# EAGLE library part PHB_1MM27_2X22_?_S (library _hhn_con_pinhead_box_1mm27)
Pin Header Box-Type, 1.27mm/0.5"/50mil Pitch, 2x22 Circuits, single gates in schematic Note: see library description for an important note about THT-version
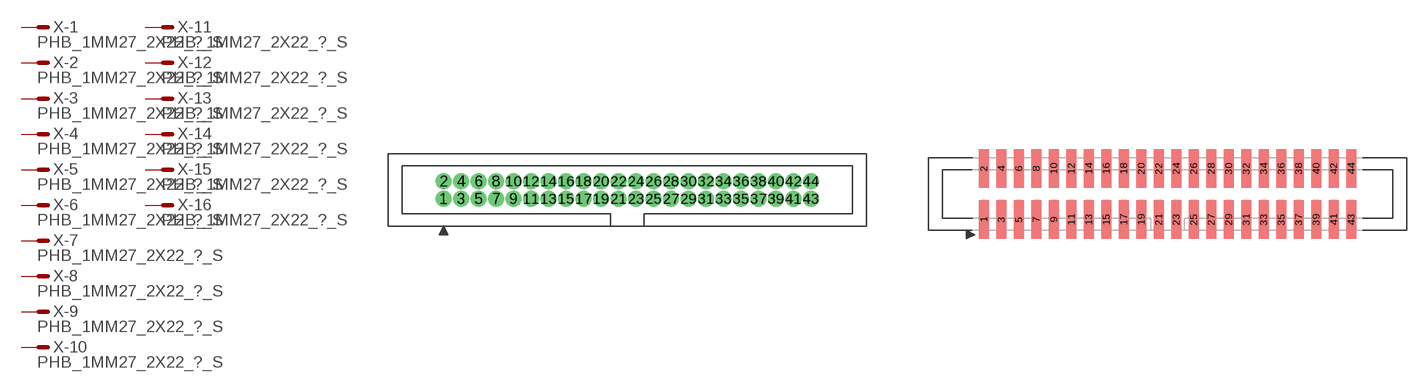
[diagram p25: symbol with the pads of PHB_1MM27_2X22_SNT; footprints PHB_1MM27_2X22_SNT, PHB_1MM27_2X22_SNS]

Designator prefix X; gates -1=M -2=M -3=M -4=M -5=M -6=M -7=M -8=M -9=M -10=M -11=M -12=M -13=M -14=M -15=M -16=M -17=M -18=M -19=M -20=M -21=M -22=M -23=M -24=M -25=M -26=M -27=M -28=M -29=M -30=M -31=M -32=M -33=M -34=M -35=M -36=M -37=M -38=M -39=M -40=M -41=M -42=M -43=M -44=M

## PHB_1MM27_2X22_SNT_S  [PHB_1MM27_2X22_SNT]
1  -1:S  pas
2  -2:S  pas
3  -3:S  pas
4  -4:S  pas
5  -5:S  pas
6  -6:S  pas
7  -7:S  pas
8  -8:S  pas
9  -9:S  pas
10  -10:S  pas
11  -11:S  pas
12  -12:S  pas
13  -13:S  pas
14  -14:S  pas
15  -15:S  pas
16  -16:S  pas
17  -17:S  pas
18  -18:S  pas
19  -19:S  pas
20  -20:S  pas
21  -21:S  pas
22  -22:S  pas
23  -23:S  pas
24  -24:S  pas
25  -25:S  pas
26  -26:S  pas
27  -27:S  pas
28  -28:S  pas
29  -29:S  pas
30  -30:S  pas
31  -31:S  pas
32  -32:S  pas
33  -33:S  pas
34  -34:S  pas
35  -35:S  pas
36  -36:S  pas
37  -37:S  pas
38  -38:S  pas
39  -39:S  pas
40  -40:S  pas
41  -41:S  pas
42  -42:S  pas
43  -43:S  pas
44  -44:S  pas

## PHB_1MM27_2X22_SNS_S  [PHB_1MM27_2X22_SNS]
Pads as for PHB_1MM27_2X22_SNT

## Footprint PHB_1MM27_2X22_SNT (pad centres in mm)
Pin Header Box-Type, 1.27mm Pitch, 2x22 circuits, Straight, No Locking, THT Important Note: Diameter in this lbr is set to a specific value (NOT 'auto' = 0), this is ignored by actual eagle versions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
drill 0.65 pad 1 round: 1 -13.335,-0.635; 2 -13.335,0.635; 3 -12.065,-0.635; 4 -12.065,0.635; 5 -10.795,-0.635; 6 -10.795,0.635; 7 -9.525,-0.635; 8 -9.525,0.635; 9 -8.255,-0.635; 10 -8.255,0.635; 11 -6.985,-0.635; 12 -6.985,0.635; 13 -5.715,-0.635; 14 -5.715,0.635; 15 -4.445,-0.635; 16 -4.445,0.635; 17 -3.175,-0.635; 18 -3.175,0.635; 19 -1.905,-0.635; 20 -1.905,0.635; 21 -0.635,-0.635; 22 -0.635,0.635; 23 0.635,-0.635; 24 0.635,0.635; 25 1.905,-0.635; 26 1.905,0.635; 27 3.175,-0.635; 28 3.175,0.635; 29 4.445,-0.635; 30 4.445,0.635; 31 5.715,-0.635; 32 5.715,0.635; 33 6.985,-0.635; 34 6.985,0.635; 35 8.255,-0.635; 36 8.255,0.635; 37 9.525,-0.635; 38 9.525,0.635; 39 10.795,-0.635; 40 10.795,0.635; 41 12.065,-0.635; 42 12.065,0.635; 43 13.335,-0.635; 44 13.335,0.635

## Footprint PHB_1MM27_2X22_SNS (pad centres in mm)
Pin Header Box-Type, 1.27mm Pitch, 2x22 circuits, Straight, No Locking, SMT
smd 0.76 x 2.8: 1 -13.335,-1.85; 2 -13.335,1.85; 3 -12.065,-1.85; 4 -12.065,1.85; 5 -10.795,-1.85; 6 -10.795,1.85; 7 -9.525,-1.85; 8 -9.525,1.85; 9 -8.255,-1.85; 10 -8.255,1.85; 11 -6.985,-1.85; 12 -6.985,1.85; 13 -5.715,-1.85; 14 -5.715,1.85; 15 -4.445,-1.85; 16 -4.445,1.85; 17 -3.175,-1.85; 18 -3.175,1.85; 19 -1.905,-1.85; 20 -1.905,1.85; 21 -0.635,-1.85; 22 -0.635,1.85; 23 0.635,-1.85; 24 0.635,1.85; 25 1.905,-1.85; 26 1.905,1.85; 27 3.175,-1.85; 28 3.175,1.85; 29 4.445,-1.85; 30 4.445,1.85; 31 5.715,-1.85; 32 5.715,1.85; 33 6.985,-1.85; 34 6.985,1.85; 35 8.255,-1.85; 36 8.255,1.85; 37 9.525,-1.85; 38 9.525,1.85; 39 10.795,-1.85; 40 10.795,1.85; 41 12.065,-1.85; 42 12.065,1.85; 43 13.335,-1.85; 44 13.335,1.85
